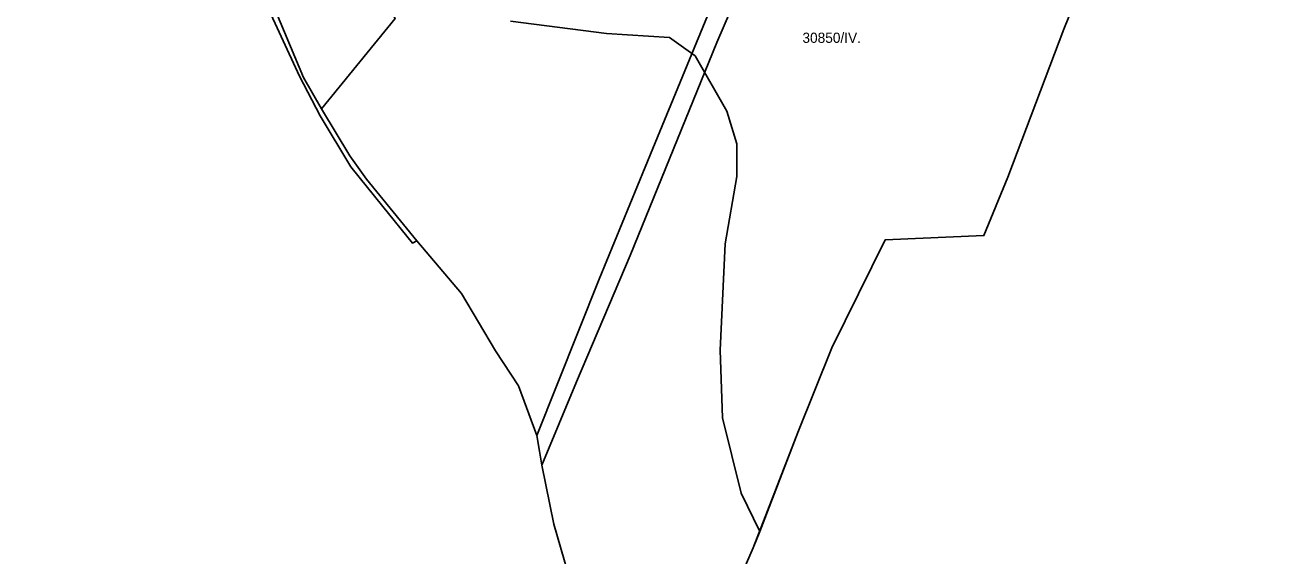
# Model space of a CAD drawing. Extents: x -532083 to -529270, y -1180561 to -1176456.
# Drawn here: x -531261 to -530644, y -1179687 to -1179427 of the extents above; entities that cross this region are included whole.
import ezdxf

# ---------------------------------------------------------------- set-up
doc = ezdxf.new("R2010")
doc.units = 0
for name, color, linetype in [('95560013', 7, 'Continuous'), ('95620013', 7, 'Continuous'), ('95660013', 7, 'Continuous')]:
    doc.layers.add(name, color=color, linetype=linetype)

msp = doc.modelspace()

# ---------------------------------------------------------------- linework, layer by layer
at = {"layer": '95560013'}
for points in [[(-530982.2063, -1179740.95245), (-531002.4393, -1179671.14445), (-531008.2583, -1179642.17845), (-530991.3113, -1179601.48545), (-530965.1553, -1179539.63945), (-530922.7333, -1179435.44145), (-530912.8693, -1179412.60445), (-530868.8573, -1179308.31745), (-530841.6463, -1179248.37045), (-530828.3473, -1179220.63445), (-530808.7483, -1179188.33545), (-530790.8993, -1179152.17445), (-530770.9513, -1179116.36445), (-530755.5653, -1179095.46845), (-530713.8673, -1179045.84445), (-530638.6183, -1179062.40745)], [(-530624.0833, -1179110.25145), (-530692.4043, -1179279.29745), (-530711.6183, -1179327.08245), (-530752.8893, -1179428.87345), (-530780.3383, -1179501.33545), (-530792.0203, -1179529.85045), (-530840.3343, -1179531.93145), (-530866.4173, -1179584.85745), (-530883.0153, -1179626.18745), (-530904.8823, -1179682.75545), (-530925.0953, -1179729.23645), (-530887.7793, -1179774.78045), (-530858.8613, -1179812.72545), (-530824.8703, -1179874.67145), (-530797.3943, -1179923.83045), (-530786.3453, -1179940.81745), (-530768.2873, -1179960.35245), (-530749.8763, -1179974.91445), (-530718.0113, -1179997.29145), (-530679.7723, -1180020.73345), (-530652.1383, -1180035.12045), (-530616.5163, -1180051.56345)], [(-530923.8833, -1179413.83845), (-530953.9483, -1179487.19045), (-530980.2533, -1179551.17345), (-531010.8113, -1179627.66445), (-531019.7473, -1179603.33245), (-531031.0243, -1179586.25745), (-531047.6193, -1179558.29745), (-531069.4213, -1179532.37145), (-531094.0373, -1179502.33145), (-531102.3293, -1179490.87545), (-531116.1203, -1179467.89045), (-531080.0903, -1179423.57845)]]:
    msp.add_lwpolyline(points, dxfattribs=at)
msp.add_lwpolyline([(-531116.1203, -1179467.89045), (-531124.8823, -1179452.54945), (-531140.4943, -1179415.15645), (-531154.1953, -1179391.98545), (-531197.3323, -1179318.53245), (-531232.9843, -1179254.01545), (-531251.9673, -1179218.60745), (-531261.0553, -1179200.73045), (-531235.3893, -1179170.37045), (-531228.8523, -1179164.29845), (-531230.0623, -1179183.48645), (-531203.9123, -1179223.31745), (-531144.6613, -1179315.17945), (-531117.2793, -1179356.63845), (-531080.0903, -1179423.57845)], close=True, dxfattribs=at)
at = {"layer": '95620013'}
msp.add_lwpolyline([(-530638.1853, -1179917.86845), (-530656.2083, -1179951.88945), (-530671.4873, -1179971.33845), (-530710.5303, -1179971.53645), (-530738.3333, -1179952.54645), (-530784.2593, -1179922.01445), (-530802.5813, -1179881.01145), (-530821.6083, -1179839.30245), (-530887.7793, -1179774.78045), (-530925.0953, -1179729.23645), (-530904.8823, -1179682.75545), (-530883.0153, -1179626.18745), (-530866.4173, -1179584.85745), (-530840.3343, -1179531.93145), (-530792.0203, -1179529.85045), (-530780.3383, -1179501.33545), (-530752.8893, -1179428.87345), (-530711.6183, -1179327.08245), (-530692.4043, -1179279.29745), (-530624.0833, -1179110.25145)], dxfattribs=at)
at = {"layer": '95660013'}
for points in [[(-530638.1853, -1179917.86845), (-530656.2083, -1179951.88945), (-530671.4873, -1179971.33845), (-530690.4433, -1179971.43445), (-530710.5303, -1179971.53645), (-530738.3333, -1179952.54645), (-530784.2593, -1179922.01445), (-530802.5813, -1179881.01145), (-530821.6083, -1179839.30245), (-530887.7793, -1179774.78045), (-530925.0953, -1179729.23645), (-530904.8823, -1179682.75545), (-530901.7523, -1179674.65945), (-530883.0153, -1179626.18745), (-530866.4173, -1179584.85745), (-530840.3343, -1179531.93145), (-530792.0203, -1179529.85045), (-530780.3383, -1179501.33545), (-530752.8893, -1179428.87345), (-530711.6183, -1179327.08245), (-530692.4043, -1179279.29745), (-530624.0833, -1179110.25145)], [(-530711.6183, -1179327.08245), (-530752.8893, -1179428.87345), (-530780.3383, -1179501.33545), (-530792.0203, -1179529.85045), (-530840.3343, -1179531.93145), (-530866.4173, -1179584.85745), (-530883.0153, -1179626.18745), (-530901.7523, -1179674.65945), (-530910.8123, -1179656.00045), (-530919.8753, -1179619.00045), (-530921.1253, -1179586.00045), (-530918.6253, -1179534.00045), (-530912.8753, -1179501.00045), (-530912.8753, -1179485.00045), (-530917.8123, -1179469.00045), (-530933.3753, -1179442.00045), (-530945.8123, -1179433.00045), (-530976.6873, -1179431.00045), (-531023.6873, -1179425.00045)], [(-530982.2063, -1179740.95245), (-531002.4393, -1179671.14445), (-531008.2583, -1179642.17845), (-531009.4543, -1179635.37945), (-531010.8113, -1179627.66445), (-531019.7473, -1179603.33245), (-531031.0243, -1179586.25745), (-531047.6193, -1179558.29745), (-531069.4213, -1179532.37145), (-531071.5623, -1179533.62445), (-531086.1903, -1179515.72845), (-531101.7113, -1179496.22245), (-531116.6963, -1179471.34745), (-531126.8743, -1179451.88045), (-531143.7973, -1179415.14145)], [(-531023.6873, -1179425.00045), (-530976.6873, -1179431.00045), (-530945.8123, -1179433.00045), (-530933.3753, -1179442.00045), (-530917.8123, -1179469.00045), (-530912.8753, -1179485.00045), (-530912.8753, -1179501.00045), (-530918.6253, -1179534.00045), (-530921.1253, -1179586.00045), (-530919.8753, -1179619.00045), (-530910.8123, -1179656.00045), (-530901.7523, -1179674.65945), (-530904.8823, -1179682.75545), (-530925.0953, -1179729.23645)]]:
    msp.add_lwpolyline(points, dxfattribs=at)

# ---------------------------------------------------------------- texts
msp.add_text('30850/IV.', height=5, rotation=0.00000001, dxfattribs=at).set_placement((-530880.8318, -1179435.57135))

doc.saveas('drawing.dxf')
